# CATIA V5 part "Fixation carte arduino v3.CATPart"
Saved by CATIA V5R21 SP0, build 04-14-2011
Part number: Porte carte arduino
Bounding box of the stored display mesh (mm): x -6.9 to 25, y 0 to 105, z 0 to 59.3
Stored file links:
  C:\Users\2027.DESARCY-LEMIE30\Desktop\Assemblage26.05\Fixation carte arduino v3.CATPart
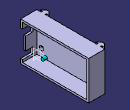
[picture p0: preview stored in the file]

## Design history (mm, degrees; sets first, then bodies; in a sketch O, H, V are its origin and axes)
Body1 (main body)
  Sketch1 on yz-plane, origin (0, 0, 0), H (0, 1, 0), V (0, 0, 1)
    line L1 (0, 0) -> (105, 0)
    line L2 (105, 0) -> (105, 59.3)
    line L3 (105, 59.3) -> (0, 59.3)
    line L4 (0, 59.3) -> (0, 0)
    length L3 = 105
    length L2 = 59.3
    horizontal: L1 H, L3 H
    vertical: L2 V, L4 V
  Pad1: profile Sketch1, direction (1, 0, 0), length 20
  Sketch2 on end face of Pad1, origin (20, 0, 0), H (0, 1, 0), V (0, 0, 1)
    line L1 (3, 3) -> (102, 3)
    line L2 (102, 3) -> (102, 56.3)
    line L3 (102, 56.3) -> (3, 56.3)
    line L4 (3, 56.3) -> (3, 3)
    reference projected line E1 (105, 0) -> (105, 59) from edge [face of Pad1 from Sketch1.L2 | end face of Pad1]
    reference projected line E2 (108.5, 59.3) -> (0, 59.3) from edge [face of Pad1 from Sketch1.L3 | end face of Pad1]
    reference projected line E3 (0, 59.3) -> (0, 0) from edge [face of Pad1 from Sketch1.L4 | end face of Pad1]
    reference projected line E4 (0, 0) -> (105, 0) from edge [face of Pad1 from Sketch1.L1 | end face of Pad1]
    distance L2 E1 = 3
    distance L3 E2 = 3
    distance L4 E3 = 3
    distance L1 E4 = 3
    horizontal: L1 H, L3 H
    vertical: L2 V, L4 V
  Pocket1: profile Sketch2, direction (-1, 0, 0), length 17
  Sketch3 on face of Pad1 from Sketch1.L3, origin (0, 0, 59.3), H (1, 0, 0), V (0, 1, 0)
    point P1 (0, 98.1)
    line L1 (0, 98.1) -> (-2, 98.1)
    point P2 (-2, 98.1)
    line L2 (-2, 98.1) -> (-2, 101.9)
    point P3 (-2, 101.9)
    line L3 (-2, 101.9) -> (-6.9, 97)
    point P4 (-6.9, 97)
    line L4 (-6.9, 97) -> (-6.9, 95.1)
    point P5 (-6.9, 95.1)
    construction line L5 (-42.3956, 95.1) -> (20, 95.1)
    point P7 (20, 95.1)
    reference projected line E1 (0, 105) -> (0, 0) from edge [start face of Pad1 | face of Pad1 from Sketch1.L3]
    reference projected line E2 (20, 105) -> (20, 0) from edge [face of Pad1 from Sketch1.L3 | end face of Pad1]
    point P8 (-6.9, 95.1)
    point P9 (-6.9, 93.2)
    line L6 (-6.9, 93.2) -> (-6.9, 95.1)
    point P10 (-2, 88.3)
    line L7 (-2, 88.3) -> (-6.9, 93.2)
    point P11 (-2, 92.1)
    line L8 (-2, 92.1) -> (-2, 88.3)
    point P12 (0, 92.1)
    line L9 (0, 92.1) -> (-2, 92.1)
    axis line L10 (-12.7576, 52.5) -> (34.0087, 52.5)
    line L11 (0, 98.1) -> (0, 92.1)
    point P15 (0, 6.9)
    point P16 (-2, 6.9)
    point P17 (-2, 3.1)
    point P18 (-6.9, 8)
    point P19 (-6.9, 9.9)
    point P20 (-6.9, 9.9)
    point P21 (-6.9, 11.8)
    point P22 (-2, 16.7)
    point P23 (-2, 12.9)
    point P24 (0, 12.9)
    line L12 (0, 6.9) -> (-2, 6.9)
    line L13 (-2, 6.9) -> (-2, 3.1)
    line L14 (-2, 3.1) -> (-6.9, 8)
    line L15 (-6.9, 8) -> (-6.9, 9.9)
    line L16 (-6.9, 11.8) -> (-6.9, 9.9)
    line L17 (-2, 16.7) -> (-6.9, 11.8)
    line L18 (-2, 12.9) -> (-2, 16.7)
    line L19 (0, 12.9) -> (-2, 12.9)
    line L20 (0, 6.9) -> (0, 12.9)
    reference projected line E3 (0, 105) -> (20, 105) from edge [face of Pad1 from Sketch1.L3 | face of Pad1 from Sketch1.L2]
    reference projected line E4 (0, 105) -> (20, 105) from edge [face of Pad1 from Sketch1.L3 | face of Pad1 from Sketch1.L2]
    distance L1 L5 = 3
    length L2 = 3.8
    angle L3 L2 = 45
    length L4 = 1.9
    distance L4 L11 = 6.9
    distance E3 L10 = 52.5
    distance L1 E4 = 6.9
    coincidence: P1 V, P5 L5, P1 E1, P7 E2, L4 L6, P5 P8
    horizontal: L1 H, L5 H, L10 H
    vertical: L2 V, L4 V, L11 V
    symmetry: P5 P8 L5, P4 P9 L5, L4 L6 L5, P3 P10 L5, L3 L7 L5, P2 P11 L5, L2 L8 L5, P1 P12 L5, L1 L9 L5, P1 P15 L10, P2 P16 L10, P3 P17 L10, P4 P18 L10, P5 P19 L10, P8 P20 L10, P9 P21 L10, P10 P22 L10, P11 P23 L10, P12 P24 L10, L1 L12 L10, L2 L13 L10, L3 L14 L10, L4 L15 L10, L6 L16 L10, L7 L17 L10, L8 L18 L10, L9 L19 L10, L11 L20 L10
  Pad2: profile Sketch3, direction (0, 0, -1), length 59
  Sketch4 on end face of Pocket1, origin (3, 16.9157, 27.9903), H (0, 1, 0), V (0, 0, 1)
    point P1 (78.1843, 16.2597)
    construction line L1 (35.5843, 31.3097) -> (35.5843, -27.9903)
    point P2 (35.5843, 31.3097)
    point P3 (35.5843, -27.9903)
    reference projected line E1 (88.0843, -27.9903) -> (88.0843, 31.0097) from edge [face of Pad1 from Sketch1.L2 | end face of Pad1]
    reference projected line E2 (91.5843, 31.3097) -> (-16.9157, 31.3097) from edge [face of Pad1 from Sketch1.L3 | end face of Pad1]
    reference projected line E3 (-16.9157, -27.9903) -> (88.0843, -27.9903) from edge [face of Pad1 from Sketch1.L1 | end face of Pad1]
    construction line L2 (35.5843, 1.6597) -> (88.0843, 1.6597)
    point P4 (35.5843, 1.6597)
    point P5 (88.0843, 1.6597)
    reference projected line E4 (88.0843, -27.9903) -> (88.0843, 31.0097) from edge [face of Pad1 from Sketch1.L2 | end face of Pad1]
    axis line L3 (78.1843, 1.6597) -> (78.1843, 30.8597)
    point P6 (78.1843, 1.6597)
    reference projected line E5 (88.0843, -27.9903) -> (88.0843, 31.3097) from edge [face of Pad1 from Sketch1.L2 | end face of Pad1]
    distance L1 E1 = 52.5
    distance P1 E5 = 9.9
    vertical: L1 V, L3 V
    coincidence: P2 E2, P3 E3, P5 E4, P6 L2
    horizontal: L2 H
    midpoint: P4 L1, P1 L3
  Hole1: placed by Sketch4, at (3, 95.1, 44.25) direction (-1, 0, 0), diameter 3.8, depth 12, counterbore diameter 6.8, counterbore depth 4
  RectPattern1: of Hole1, direction 1 instances 2, spacing 84.8, along start face of Pad1 reversed, direction 2 instances 2, spacing 29.5, along start face of Pad1
  Sketch5 on face of Pad1 from Sketch1.L4, origin (0, 0, 0), H (1, 0, 0), V (0, 0, 1)
    line L1 (9, 47.5) -> (20, 47.5)
    line L2 (20, 47.5) -> (20, 35.5)
    line L3 (20, 35.5) -> (9, 35.5)
    line L4 (9, 35.5) -> (9, 47.5)
    reference projected line E1 (20, 59.3) -> (20, 0) from edge [face of Pad1 from Sketch1.L4 | end face of Pad1]
    reference projected line E2 (0, 59.3) -> (20, 59.3) from edge [face of Pad1 from Sketch1.L4 | face of Pad1 from Sketch1.L3]
    line L5 (9, 15.8) -> (20, 15.8)
    line L6 (20, 15.8) -> (20, 6.8)
    line L7 (20, 6.8) -> (9, 6.8)
    line L8 (9, 6.8) -> (9, 15.8)
    reference projected line E3 (20, 59.3) -> (20, 0) from edge [face of Pad1 from Sketch1.L4 | end face of Pad1]
    reference projected line E4 (0, 59.3) -> (20, 59.3) from edge [face of Pad1 from Sketch1.L4 | face of Pad1 from Sketch1.L3]
    reference projected line E5 (0, 0) -> (20, 0) from edge [face of Pad1 from Sketch1.L1 | face of Pad1 from Sketch1.L4]
    reference projected point E6 (20, 56.3) from edge [end face of Pad1 | face of Pocket1 from Sketch2.L3]
    reference projected point E7 (20, 3) from edge [end face of Pad1 | face of Pocket1 from Sketch2.L1]
    length L1 = 11
    length L2 = 12
    distance L1 E2 = 11.8
    length L6 = 9
    length L5 = 11
    distance L3 L5 = 19.7
    distance E4 E5 = 59.3 (reference)
    distance E6 E7 = 53.3 (reference)
    horizontal: L1 H, L3 H, L5 H, L7 H
    vertical: L2 V, L4 V, L6 V, L8 V
    coincidence: E1 L2, E3 L6
  Pocket2: profile Sketch5, direction (0, 1, 0), through (limit type 6)
  Sketch6 on end face of Pocket1, origin (3, 0, 0), H (0, 1, 0), V (0, 0, 1)
    circle A1 centre (17, 5.5) radius 2.5
    point P1 (17, 5.5)
    circle A2 centre (91.9, 53.8) radius 2.5
    point P2 (91.9, 53.8)
    reference projected line E1 (3, 3) -> (102, 3) from edge [end face of Pad1 | face of Pocket1 from Sketch2.L1]
    reference projected line E2 (3, 56.3) -> (3, 3) from edge [end face of Pocket1 | face of Pocket1 from Sketch2.L4]
    radius A2 = 2.5
    radius A1 = 2.5
    distance P1 P2 H = 74.9
    distance P2 P1 V = 48.3
    distance P1 E1 = 2.5
    distance P1 E2 = 14
  Pad3: profile Sketch6, direction (1, 0, 0), length 5
  Pad4: profile end face of Pad1, direction along end face of Pad1, length 5, opposite side length 2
